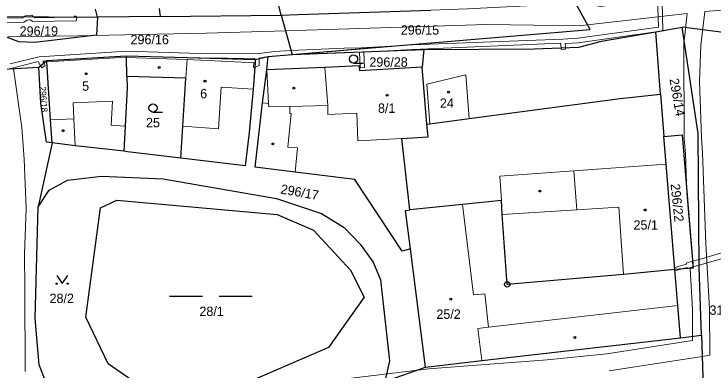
# Model space of a CAD drawing. Extents: x -769392 to -767038, y -1018329 to -1015269.
# Drawn here: x -768574.3 to -768447.4, y -1016338.1 to -1016273.5 of the extents above; entities that cross this region are included whole.
import ezdxf
from ezdxf.enums import TextEntityAlignment as Align

# ---------------------------------------------------------------- set-up
doc = ezdxf.new("R2010")
doc.units = 0
doc.header["$LTSCALE"] = 0.68
for name, color, linetype, lineweight in [('1', 7, 'Continuous', 25), ('13', 7, 'Continuous', 13), ('3', 7, 'Continuous', 25), ('4', 7, 'Continuous', 13), ('5', 7, 'Continuous', 25), ('8', 7, 'Continuous', 25)]:
    doc.layers.add(name, color=color, linetype=linetype, lineweight=lineweight)
doc.layers.add('2', color=7, linetype='Continuous')

msp = doc.modelspace()

# ---------------------------------------------------------------- linework, layer by layer
at = {"layer": '1'}
for p, q in [((-768525.85, -1016273.77), (-768526.59, -1016270.75)), ((-768469.86, -1016276.35), (-768472.78, -1016271.11)), ((-768559.15, -1016274.1), (-768559.49, -1016272.66)), ((-768547.99, -1016272.52), (-768547.78, -1016273.99)), ((-768522.75, -1016273.66), (-768498.76, -1016272.82)), ((-768573.42, -1016278.56), (-768585.84, -1016273.96)), ((-768585.84, -1016273.96), (-768559.15, -1016274.1)), ((-768559.15, -1016274.1), (-768559.31, -1016277.38)), ((-768547.78, -1016273.99), (-768559.15, -1016274.1)), ((-768547.78, -1016273.99), (-768525.85, -1016273.77)), ((-768525.85, -1016273.77), (-768522.75, -1016273.66)), ((-768525.85, -1016273.77), (-768523.89, -1016280.87)), ((-768457.98, -1016276.75), (-768453.2, -1016275.91)), ((-768434, -1016278.4), (-768453.2, -1016275.91)), ((-768450.31, -1016295.22), (-768453.2, -1016275.91)), ((-768523.89, -1016280.87), (-768469.86, -1016276.35)), ((-768467.83, -1016278.49), (-768457.98, -1016276.75)), ((-768457.12, -1016288.05), (-768457.98, -1016276.75)), ((-768559.31, -1016277.38), (-768570.47, -1016278.68)), ((-768570.47, -1016278.68), (-768573.42, -1016278.56)), ((-768480.02, -1016279.86), (-768471.91, -1016279.55)), ((-768471.91, -1016279.55), (-768467.83, -1016278.49)), ((-768528.19, -1016281.27), (-768523.89, -1016280.87)), ((-768523.89, -1016280.87), (-768499.98, -1016279.99)), ((-768499.98, -1016279.99), (-768500.28, -1016283.15)), ((-768499.98, -1016279.99), (-768480.02, -1016279.86)), ((-768569.79, -1016283.19), (-768568.3, -1016281.94)), ((-768568.31, -1016282.2), (-768568.3, -1016281.94)), ((-768567.64, -1016292.73), (-768568.31, -1016282.2)), ((-768568.3, -1016281.94), (-768553.92, -1016281.13)), ((-768553.92, -1016281.13), (-768542.87, -1016281.42)), ((-768553.9, -1016281.34), (-768553.92, -1016281.13)), ((-768553.89, -1016281.43), (-768553.9, -1016281.34)), ((-768553.83, -1016284.86), (-768553.89, -1016281.43)), ((-768542.87, -1016281.42), (-768530.56, -1016281.8)), ((-768530.56, -1016281.8), (-768530.58, -1016282.38)), ((-768530.56, -1016281.8), (-768528.19, -1016281.27)), ((-768528.46, -1016283.66), (-768528.19, -1016281.27)), ((-768579.53, -1016283.75), (-768569.79, -1016283.19)), ((-768569.39, -1016289.73), (-768569.79, -1016283.19)), ((-768530.58, -1016282.38), (-768530.92, -1016287.14)), ((-768517.97, -1016283.22), (-768528.46, -1016283.66)), ((-768511.66, -1016282.96), (-768517.97, -1016283.22)), ((-768511.61, -1016283.85), (-768511.66, -1016282.96)), ((-768500.28, -1016283.15), (-768511.61, -1016283.85)), ((-768499.45, -1016293.5), (-768500.28, -1016283.15)), ((-768529.26, -1016289.64), (-768528.46, -1016283.66)), ((-768543.16, -1016285.18), (-768553.83, -1016284.86)), ((-768553.83, -1016284.86), (-768553.74, -1016286.9)), ((-768543.7, -1016293.86), (-768543.16, -1016285.18)), ((-768553.74, -1016286.9), (-768554.12, -1016293.9)), ((-768530.92, -1016287.14), (-768531.63, -1016295.04)), ((-768464.4, -1016288.85), (-768457.12, -1016288.05)), ((-768457.12, -1016288.05), (-768456.49, -1016295.73)), ((-768568.37, -1016296.75), (-768569.39, -1016289.73)), ((-768530.54, -1016301.31), (-768529.26, -1016289.64)), ((-768491.79, -1016292.47), (-768464.4, -1016288.85)), ((-768567.38, -1016296.88), (-768567.64, -1016292.73)), ((-768499.45, -1016293.5), (-768498.91, -1016293.45)), ((-768499.24, -1016295.81), (-768499.45, -1016293.5)), ((-768498.91, -1016293.45), (-768491.79, -1016292.47)), ((-768554.12, -1016293.9), (-768554.36, -1016298.43)), ((-768544.06, -1016299.67), (-768543.7, -1016293.86)), ((-768531.63, -1016295.04), (-768532.37, -1016301.09)), ((-768503.99, -1016296.09), (-768499.24, -1016295.81)), ((-768502.56, -1016309.06), (-768503.99, -1016296.09)), ((-768456.49, -1016295.73), (-768453.2, -1016295.46)), ((-768456.09, -1016300.75), (-768456.49, -1016295.73)), ((-768453.2, -1016295.46), (-768451.22, -1016319.61)), ((-768450.12, -1016319.52), (-768450.31, -1016295.22)), ((-768567.38, -1016296.88), (-768569.91, -1016308.52)), ((-768567.38, -1016296.88), (-768568.37, -1016296.75)), ((-768563.17, -1016297.43), (-768567.38, -1016296.88)), ((-768557.03, -1016298.13), (-768563.17, -1016297.43)), ((-768554.36, -1016298.43), (-768557.03, -1016298.13)), ((-768553.71, -1016298.5), (-768554.36, -1016298.43)), ((-768544.06, -1016299.67), (-768553.71, -1016298.5)), ((-768532.37, -1016301.09), (-768544.06, -1016299.67)), ((-768523.29, -1016302.21), (-768530.54, -1016301.31)), ((-768454.51, -1016319.88), (-768456.09, -1016300.75)), ((-768512.52, -1016303.52), (-768523.29, -1016302.21)), ((-768567.92, -1016305.47), (-768564.6, -1016303.64)), ((-768564.6, -1016303.64), (-768558.4, -1016302.95)), ((-768558.4, -1016302.95), (-768547.26, -1016303.44)), ((-768547.26, -1016303.44), (-768526.73, -1016306.98)), ((-768503.93, -1016316.51), (-768512.52, -1016303.52)), ((-768569.91, -1016308.52), (-768567.92, -1016305.47)), ((-768558.58, -1016308.65), (-768555.62, -1016307.26)), ((-768555.62, -1016307.26), (-768526.56, -1016309.87)), ((-768526.73, -1016306.98), (-768518.52, -1016309.69)), ((-768485.95, -1016307.34), (-768492.98, -1016308.07)), ((-768485.79, -1016309.87), (-768485.95, -1016307.34)), ((-768570.46, -1016328.73), (-768569.91, -1016308.52)), ((-768561.23, -1016328.48), (-768558.58, -1016308.65)), ((-768492.98, -1016308.07), (-768502.56, -1016309.06)), ((-768526.56, -1016309.87), (-768520.02, -1016312.75)), ((-768518.52, -1016309.69), (-768514.46, -1016312.22)), ((-768503.3, -1016309.14), (-768502.56, -1016309.06)), ((-768502.43, -1016316.1), (-768503.3, -1016309.14)), ((-768484.89, -1016322.55), (-768485.79, -1016309.87)), ((-768514.46, -1016312.22), (-768511.53, -1016315.28)), ((-768520.02, -1016312.75), (-768513.29, -1016319.97)), ((-768511.53, -1016315.28), (-768509.17, -1016318.52)), ((-768502.43, -1016316.1), (-768503.93, -1016316.51)), ((-768499.68, -1016337.53), (-768502.43, -1016316.1)), ((-768509.17, -1016318.52), (-768507.84, -1016321.71)), ((-768513.29, -1016319.97), (-768510.8, -1016324.84)), ((-768454.51, -1016319.88), (-768463.79, -1016320.78)), ((-768451.22, -1016319.61), (-768454.51, -1016319.88)), ((-768453.99, -1016326.35), (-768454.51, -1016319.88)), ((-768449.71, -1016331.77), (-768450.12, -1016319.52)), ((-768463.79, -1016320.78), (-768484.89, -1016322.55)), ((-768507.84, -1016321.71), (-768506.25, -1016336.41)), ((-768510.8, -1016324.84), (-768517.25, -1016334.01)), ((-768453.51, -1016332.21), (-768453.99, -1016326.35)), ((-768569.72, -1016337.14), (-768570.46, -1016328.73)), ((-768557.2, -1016336.94), (-768561.23, -1016328.48)), ((-768489.51, -1016336.36), (-768453.51, -1016332.21)), ((-768453.51, -1016332.21), (-768449.71, -1016331.77)), ((-768449.71, -1016331.77), (-768449.35, -1016342.79)), ((-768517.25, -1016334.01), (-768538.7, -1016343.21)), ((-768506.25, -1016336.41), (-768507.07, -1016340.13)), ((-768499.68, -1016337.53), (-768489.51, -1016336.36)), ((-768568.44, -1016340.39), (-768569.72, -1016337.14)), ((-768551.28, -1016341.04), (-768557.2, -1016336.94)), ((-768507.07, -1016340.13), (-768499.68, -1016337.53))]:
    msp.add_line(p, q, dxfattribs=at)
at = {"layer": '13'}
for points in [[(-768438.59, -1016268.98), (-768453.04, -1016270.15), (-768458.42, -1016270.59), (-768464.2, -1016271.71), (-768468.02, -1016272.16), (-768472.78, -1016271.11), (-768470.32, -1016275.52), (-768452.26, -1016273.45), (-768452.82, -1016278.43), (-768450.31, -1016295.22), (-768450.12, -1016319.52), (-768449.71, -1016331.77), (-768449.58, -1016335.6), (-768448.17, -1016335.38), (-768448.24, -1016327), (-768448.89, -1016315.19), (-768449.5, -1016298.7), (-768449.71, -1016295.97), (-768450.07, -1016285.71), (-768449.8, -1016279.21), (-768449.1, -1016273.07), (-768429.05, -1016271.47)], [(-768457.64, -1016270.62), (-768457.47, -1016275.91), (-768472.11, -1016277.94), (-768474.84, -1016278.09), (-768502.1, -1016279.15), (-768506.05, -1016279.38), (-768523.89, -1016280.87), (-768514.43, -1016280.51), (-768511.67, -1016280.48), (-768511.56, -1016283.29), (-768510.76, -1016283.25), (-768510.87, -1016280.46), (-768502.06, -1016279.95), (-768475.21, -1016278.85), (-768475.13, -1016279.67), (-768474.32, -1016279.64), (-768474.4, -1016278.87), (-768472.03, -1016278.74), (-768457.98, -1016276.75), (-768456.66, -1016276.52), (-768456.82, -1016271.33)], [(-768466.44, -1016338.2), (-768449.58, -1016335.6), (-768449.71, -1016331.77), (-768450.12, -1016319.52), (-768450.31, -1016295.22), (-768452.82, -1016278.43), (-768452.88, -1016278.93), (-768452.81, -1016296.14), (-768452.6, -1016298.88), (-768452.34, -1016306), (-768451.22, -1016319.61), (-768451.75, -1016319.65), (-768451.34, -1016327.1), (-768451.29, -1016332.72), (-768466.84, -1016335.12), (-768477.65, -1016336.2), (-768492, -1016337.29), (-768499.08, -1016337.83), (-768520.1, -1016340.42)], [(-768574.85, -1016283.4), (-768569.87, -1016282.17), (-768569.45, -1016282.91), (-768568.86, -1016282.41), (-768569.03, -1016282.06), (-768568.39, -1016282.02), (-768568.3, -1016281.94), (-768553.92, -1016281.13), (-768542.87, -1016281.42), (-768540.53, -1016281.48), (-768530.63, -1016281.58), (-768530.62, -1016281.8), (-768530.56, -1016281.8), (-768529.83, -1016281.64), (-768529.83, -1016281.53), (-768528.19, -1016281.27), (-768523.89, -1016280.87), (-768524.08, -1016280.17), (-768527.04, -1016280.31), (-768530.25, -1016280.78), (-768540.51, -1016280.68), (-768553.9, -1016280.27), (-768569.72, -1016281.3), (-768574.97, -1016282.6)], [(-768572.26, -1016338.32), (-768572.31, -1016323.42), (-768572.34, -1016317.04), (-768572.04, -1016308.8), (-768572.43, -1016299.83), (-768572.83, -1016294.11), (-768574.38, -1016283.45)]]:
    msp.add_lwpolyline(points, dxfattribs=at)
for points in [[(-768488.6, -1016275.46), (-768471.55, -1016275.66), (-768470.32, -1016275.52), (-768472.78, -1016271.11), (-768476.68, -1016271.84), (-768492.08, -1016272.62), (-768498.76, -1016272.82), (-768522.75, -1016273.66), (-768525.85, -1016273.77), (-768525.07, -1016276.6), (-768517.45, -1016276.37)], [(-768562.71, -1016277.52), (-768560.04, -1016277.46), (-768559.31, -1016277.38), (-768559.15, -1016274.1), (-768585.84, -1016273.96), (-768575.27, -1016277.87), (-768575.3, -1016277.7)], [(-768583.42, -1016274.43), (-768583.41, -1016274.86), (-768582.47, -1016275.21), (-768572.49, -1016275.05), (-768571.9, -1016274.64), (-768571.31, -1016274.6), (-768570.93, -1016274.92), (-768562.98, -1016274.76), (-768562.81, -1016274.11), (-768563.03, -1016274.11), (-768563.02, -1016273.92), (-768563.37, -1016273.91), (-768563.38, -1016274.12), (-768570.5, -1016274.24), (-768571.05, -1016273.78), (-768572.17, -1016273.86), (-768572.75, -1016274.25)], [(-768547.78, -1016273.99), (-768559.15, -1016274.1), (-768559.31, -1016277.38), (-768560.04, -1016277.46), (-768539.42, -1016277.04), (-768525.07, -1016276.6), (-768525.85, -1016273.77)], [(-768514.45, -1016279.71), (-768524.08, -1016280.17), (-768523.89, -1016280.87), (-768506.05, -1016279.38), (-768511.3, -1016279.68)], [(-768474.3, -1016279.89), (-768474.32, -1016279.64), (-768475.13, -1016279.67), (-768475.1, -1016280)], [(-768553.92, -1016281.13), (-768568.3, -1016281.94), (-768568.3, -1016282.01)], [(-768530.56, -1016281.8), (-768530.57, -1016282.35), (-768530.64, -1016283.26), (-768530.63, -1016283.26), (-768529.85, -1016282.86), (-768529.83, -1016281.64)], [(-768568.86, -1016282.41), (-768569.45, -1016282.91), (-768569.24, -1016283.28), (-768568.64, -1016282.88)], [(-768530.88, -1016283.23), (-768530.64, -1016283.26), (-768530.57, -1016282.35), (-768530.83, -1016282.34)], [(-768441.71, -1016316.64), (-768441.72, -1016315.59), (-768450.13, -1016318.03), (-768450.12, -1016319.07)], [(-768454.53, -1016319.47), (-768454.51, -1016319.88), (-768453.41, -1016319.79), (-768452.26, -1016319.48), (-768452.2, -1016319.67), (-768451.24, -1016319.39), (-768451.32, -1016318.37), (-768452.48, -1016318.71), (-768452.42, -1016318.9)], [(-768450.12, -1016319.07), (-768450.13, -1016318.03), (-768451.32, -1016318.37), (-768451.24, -1016319.39)], [(-768453.41, -1016319.79), (-768454.51, -1016319.88), (-768454.49, -1016320.08)]]:
    msp.add_lwpolyline(points, close=True, dxfattribs=at)
at = {"layer": '3'}
for p, q in [((-768512.743, -1016282.46), (-768510.993, -1016282.46)), ((-768549.083, -1016291.34), (-768547.333, -1016291.34)), ((-768546.099, -1016324.7), (-768540.099, -1016324.7)), ((-768537.099, -1016324.7), (-768531.099, -1016324.7))]:
    msp.add_line(p, q, dxfattribs=at)
msp.add_lwpolyline([(-768566.54, -1016320.919), (-768565.54, -1016322.42), (-768564.54, -1016320.919)], dxfattribs=at)
for centre, radius in [((-768512.7429, -1016281.7098), 0.75), ((-768549.0829, -1016290.5898), 0.75), ((-768566.54, -1016322.4195), 0.1), ((-768564.54, -1016322.4195), 0.1)]:
    msp.add_circle(centre, radius, dxfattribs=at)
at = {"layer": '4'}
for p, q in [((-768568.31, -1016282.2), (-768553.9, -1016281.34)), ((-768542.91, -1016281.76), (-768553.89, -1016281.43)), ((-768542.91, -1016281.76), (-768543.16, -1016285.18)), ((-768530.58, -1016282.38), (-768542.91, -1016281.76)), ((-768517.39, -1016290.14), (-768517.97, -1016283.22)), ((-768528.13, -1016289.74), (-768528.46, -1016283.66)), ((-768536.73, -1016286.82), (-768537.23, -1016294.36)), ((-768530.92, -1016287.14), (-768536.73, -1016286.82)), ((-768498.91, -1016293.45), (-768499.48, -1016286.27)), ((-768556.42, -1016289.36), (-768563.53, -1016289.64)), ((-768563.53, -1016289.64), (-768563.4, -1016292.54)), ((-768556.68, -1016293.71), (-768556.42, -1016289.36)), ((-768528.13, -1016289.74), (-768529.26, -1016289.64)), ((-768528.1, -1016290.36), (-768528.13, -1016289.74)), ((-768524.27, -1016290.28), (-768528.1, -1016290.36)), ((-768524.27, -1016290.28), (-768524.31, -1016291.55)), ((-768517.39, -1016290.14), (-768524.27, -1016290.28)), ((-768517.37, -1016291.77), (-768517.39, -1016290.14)), ((-768524.02, -1016291.6), (-768524.63, -1016297.67)), ((-768524.31, -1016291.55), (-768524.02, -1016291.6)), ((-768512.16, -1016291.53), (-768517.37, -1016291.77)), ((-768511.98, -1016296.51), (-768512.16, -1016291.53)), ((-768563.4, -1016292.54), (-768567.64, -1016292.73)), ((-768563.4, -1016292.54), (-768563.17, -1016297.43)), ((-768554.12, -1016293.9), (-768556.68, -1016293.71)), ((-768537.23, -1016294.36), (-768543.7, -1016293.86)), ((-768503.99, -1016296.09), (-768511.98, -1016296.51)), ((-768524.63, -1016297.67), (-768522.89, -1016297.79)), ((-768522.89, -1016297.79), (-768523.29, -1016302.21)), ((-768472.8, -1016301.95), (-768456.09, -1016300.75)), ((-768486.23, -1016302.91), (-768472.8, -1016301.95)), ((-768472.8, -1016301.95), (-768472.28, -1016309.02)), ((-768485.95, -1016307.34), (-768486.23, -1016302.91)), ((-768492.98, -1016308.07), (-768490.99, -1016324.45)), ((-768464.69, -1016308.55), (-768472.28, -1016309.02)), ((-768463.79, -1016320.78), (-768464.69, -1016308.55)), ((-768472.28, -1016309.02), (-768485.79, -1016309.87)), ((-768490.99, -1016324.45), (-768488.95, -1016324.25)), ((-768488.95, -1016324.25), (-768488.26, -1016330.33)), ((-768488.26, -1016330.33), (-768453.99, -1016326.35)), ((-768488.26, -1016330.33), (-768490.22, -1016330.56)), ((-768490.22, -1016330.56), (-768489.51, -1016336.36))]:
    msp.add_line(p, q, dxfattribs=at)
msp.add_lwpolyline([(-768499.48, -1016286.27), (-768492.4, -1016284.55), (-768491.79, -1016292.47)], dxfattribs=at)
at = {"layer": '5'}
for centre in [(-768547.9668, -1016283.2592), (-768561.2168, -1016284.3592), (-768539.6568, -1016285.7092), (-768523.5668, -1016286.9892), (-768506.6568, -1016288.2792), (-768495.5468, -1016287.7292), (-768565.3468, -1016294.6892), (-768527.3568, -1016297.0992), (-768478.9768, -1016305.6292), (-768459.9068, -1016309.0692), (-768495.1068, -1016325.2292), (-768472.6368, -1016332.1792)]:
    msp.add_circle(centre, 0.175, dxfattribs=at)
at = {"layer": '8'}
for radius in [0.5, 0.0303]:
    msp.add_circle((-768484.89, -1016322.5499), radius, dxfattribs=at)

# ---------------------------------------------------------------- texts
at = {"layer": '2'}
for s, p in [('296/19', (-768569.77, -1016277.475)), ('296/15', (-768500.7, -1016277.285)), ('296/16', (-768549.68, -1016279.025)), ('296/28', (-768506.39, -1016283.105)), ('5', (-768561.29, -1016287.455)), ('6', (-768539.9, -1016288.815)), ('8/1', (-768506.73, -1016291.455)), ('24', (-768495.829, -1016290.545)), ('25', (-768549.089, -1016294.075)), ('25/1', (-768459.789, -1016312.635)), ('28/2', (-768565.619, -1016325.935)), ('28/1', (-768538.459, -1016328.285)), ('318/7', (-768445.39, -1016328.065)), ('25/2', (-768495.519, -1016328.795))]:
    msp.add_text(s, height=1.7, dxfattribs=at).set_placement(p, align=Align.CENTER)
for s, height, rotation, p in [('296/14', 1.7, 280, (-768454.8948, -1016288.7789)), ('296/18', 1.14, 274, (-768569.4724, -1016289.0502)), ('296/17', 1.7, 350, (-768522.6281, -1016306.6612)), ('296/22', 1.7, 276, (-768454.9279, -1016307.8397))]:
    msp.add_text(s, height=height, rotation=rotation, dxfattribs=at).set_placement(p, align=Align.CENTER)

doc.saveas('drawing.dxf')
